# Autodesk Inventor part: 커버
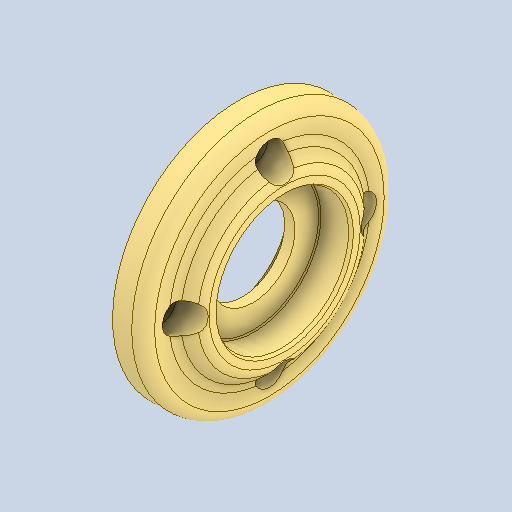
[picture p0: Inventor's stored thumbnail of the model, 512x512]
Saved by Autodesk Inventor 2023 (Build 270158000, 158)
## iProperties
Created: 2026-06
Part Number: 커버
Material: 알루미늄 6061
Document SubType Name: Modeling
Designer: 4강의실
Density: 2.7 g/cm^3
Appearance: 기본값
Author: jhkim
Sending System: Autodesk Inventor 2027
Preprocessor: ST-DEVELOPER v20.1
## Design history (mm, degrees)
feature "솔리드1"
node "솔리드2"
